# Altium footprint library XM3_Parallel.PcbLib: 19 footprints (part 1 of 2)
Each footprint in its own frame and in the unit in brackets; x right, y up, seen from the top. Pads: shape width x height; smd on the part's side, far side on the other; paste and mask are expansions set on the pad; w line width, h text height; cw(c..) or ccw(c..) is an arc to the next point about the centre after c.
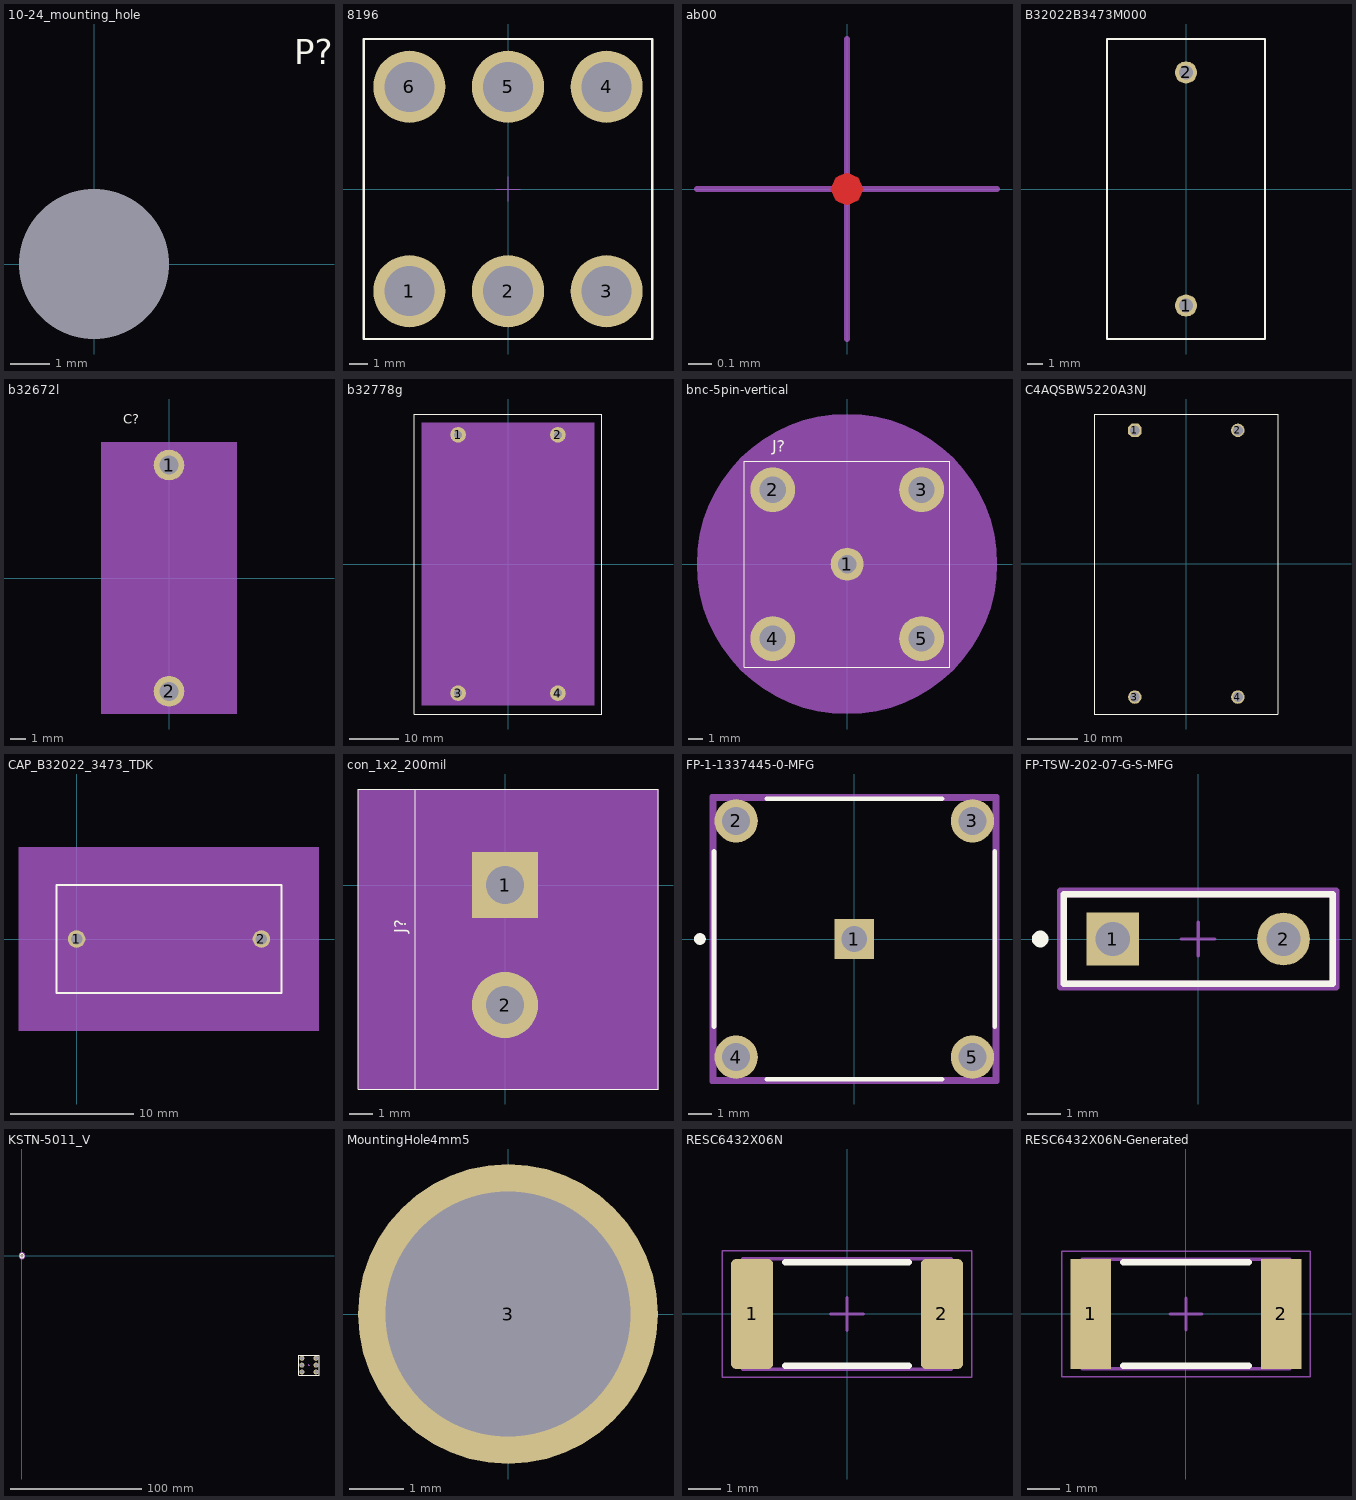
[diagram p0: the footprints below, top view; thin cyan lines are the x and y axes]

## 10-24_mounting_hole [mil]
pads (1):
  round 1 / inner round 60 / far side round 1 hole 150 square: ""(0,0)
Top Overlay:
  text "P?" at 200,200 h25
DRAWING_ORIGIN:
  lines w1: -25,0 25,0 ; 0,-25 0,25
PIN_NUMBER:

## 8196 [mil]
pads (6):
  round 150 / inner round 60 / far side round 150 hole 103.94: 1(-205,-212.5) 2(0,-212.5) 3(205,-212.5) 4(205,212.5) 5(0,212.5) 6(-205,212.5)
Top Overlay:
  lines w5: -300,311.02 -300,-311.81 300,-311.81 300,311.02 ; -300,311.81 300,311.81
DRAWING_ORIGIN:
  lines w1: -25,0 25,0 ; 0,-25 0,25
PIN_NUMBER:
  text "2" at -20,-212.5 h25
  text "6" at -225,212.5 h25
  text "5" at -20,212.5 h25
  text "3" at 185,-212.5 h25
  text "1" at -225,-212.5 h25
  text "4" at 185,212.5 h25
ASSEMBLY_TOP:
  text "J?" at 0,0 h25
3D body "8196-PCB-Conn-Color.STEP": height 453.5, standoff -216.5, extent -230.42,-278 239.58,261.95

## ab00 [mil]
TOP:
  region: 2.71,0 1.91,1.91 0,2.71 -1.26,2.18 -1.91,1.91 -2.71,0 -1.91,-1.91 -1.26,-2.18 0,-2.71 1.91,-1.91
DRAWING_ORIGIN:
  lines w1: -25,0 25,0 ; 0,-25 0,25

## B32022B3473M000 [mil]
pads (2):
  round 56 hole 36 mask+0: 1(0,-295.28) 2(0,295.28)
Top Overlay:
  lines w5: -200,-380 -180,-380 200,-380 200,380 -200,380 -200,-380
3D body "B32022B3473M000-ShortLeads.STEP": height 689.47, standoff -9.35, extent -177.17,-354.33 177.17,354.33

## b32672l [mil]
pads (2):
  round 80 / inner round 60 / far side round 80 hole 50 square: 1(0,295.28) 2(0,-295.28)
Top Overlay:
  text "C?" at -119,403.48 h25
DRAWING_ORIGIN:
  lines w1: -25,0 25,0 ; 0,-25 0,25
PIN_NUMBER:
  text "1" at -20,295.28 h25
  text "2" at -20,-295.28 h25
ASSEMBLY_TOP:
  dashed: 177.17,-354.33 177.17,354.33 -177.17,354.33 -177.17,-354.33

## b32778g [mil]
pads (4):
  round 125 / inner round 60 / far side round 125 hole 63: 1(-399.61,1033.46) 2(399.61,1033.46) 3(-399.61,-1033.46) 4(399.61,-1033.46)
Top Overlay:
  lines w5: -750,-1200 750,-1200 750,1200 -750,1200 -750,-1200
DRAWING_ORIGIN:
  lines w1: -25,0 25,0 ; 0,-25 0,25
PIN_NUMBER:
  text "4" at 379.61,-1033.46 h25
  text "1" at -419.61,1033.46 h25
  text "3" at -419.61,-1033.46 h25
  text "2" at 379.61,1033.46 h25
ASSEMBLY_TOP:
  dashed: 688.98,-1131.89 688.98,1131.89 -688.98,1131.89 -688.98,-1131.89
3D body "C4AQSBW5220A3NJ.STEP": height 1980.81, standoff -235.72, extent -697.83,-1145 700,1150.28

## bnc-5pin-vertical [mil]
pads (5):
  round 88 / inner round 60 / far side round 100 hole 50: 1(0,0)
  round 120 / inner round 60 / far side round 120 hole 70: 2(-199,199) 3(199,199) 4(-199,-199) 5(199,-199)
Top Overlay:
  lines w1: -275,-275 275,-275 275,275 -275,275 -275,-275
  text "J?" at -200,300 h31
PLACE_BOUND_TOP:
  region: 400.68,0.5 398.75,39.81 392.98,78.75 383.41,116.93 370.15,153.99 353.32,189.57 333.09,223.33 309.64,254.94 283.21,284.11 254.04,310.54 222.43,333.99 188.67,354.22 153.09,371.05 116.03,384.31 77.85,393.88 38.91,399.65 -0.4,401.58 -39.71,399.65 -78.65,393.88 -116.83,384.31 -153.89,371.05 -189.47,354.22 -200.73,347.48 -223.23,333.99 -254.84,310.54 -284.01,284.11 -310.44,254.94 -333.89,223.33 -354.12,189.57 -370.95,153.99 -384.21,116.93 -393.78,78.75 -399.55,39.81 -401.48,0.5 -399.55,-38.81 -393.78,-77.75 -384.21,-115.93 -370.95,-152.99 -354.12,-188.57 -333.89,-222.33 -310.44,-253.94 -284.01,-283.11 -254.84,-309.54 -223.23,-332.99 -200.73,-346.48 -189.47,-353.22 -153.89,-370.05 -116.83,-383.31 -78.65,-392.88 -39.71,-398.65 -0.4,-400.58 38.91,-398.65 77.85,-392.88 116.03,-383.31 153.09,-370.05 188.67,-353.22 222.43,-332.99 254.04,-309.54 283.21,-283.11 309.64,-253.94 333.09,-222.33 353.32,-188.57 370.15,-152.99 383.41,-115.93 392.98,-77.75 398.75,-38.81
  lines w1: 0,0 400,0
DRAWING_ORIGIN:
  lines w1: -25,0 25,0 ; 0,-25 0,25
PIN_NUMBER:
  text "2" at -219,199 h25
  text "5" at 179,-199 h25
  text "3" at 179,199 h25
  text "1" at -20,0 h25
  text "4" at -219,-199 h25
ASSEMBLY_TOP:
  lines w1: -275,-275 275,-275 275,275 -275,275 -275,-275
  text "J?" at -100,-175 h25
3D body: height 150, standoff 0, extent -401.48,-400.58 400.68,401.58

## C4AQSBW5220A3NJ [mm] "C4AQSBW5220A3NJ Unchecked Film; Metallized Polypropylene; DC Link; C4AQ; Automotive Grade; 22 uF; 5%; 1; 50 Film Capacitors 8.13"
pads (4):
  oct 2.65x2.65 hole 1.95: 1(-10.15,26.25)
  round 2.65 hole 1.95: 2(10.15,26.25) 3(-10.15,-26.25) 4(10.15,-26.25)
Top Overlay:
  lines w0.127: -18.161,-29.591 18.034,-29.591 18.034,29.464 -18.161,29.464 -18.161,-29.591
3D body "C4AQSBW5220A3NJ-ShortLeads.STEP": height 50.31, standoff -0.24, extent -17.725,-29.15 17.78,29.15

## CAP_B32022_3473_TDK [mil]
pads (2):
  round 56 hole 36 mask+0: 1(0,0) 2(590.55,0)
Top Overlay:
  lines w6: -64.22,-172.5 -64.22,172.5 654.78,172.5 654.78,-172.5 -64.22,-172.5
DFA_BOUND_TOP:
  region: 774.78,-292.5 -184.22,-292.5 -184.22,292.5 774.78,292.5
DRAWING_ORIGIN:
  lines w1: -59.22,-167.5 -59.22,167.5 649.78,167.5 649.78,-167.5 -59.22,-167.5
ASSEMBLY_DETAIL:
  region: 659.78,-177.5 -69.22,-177.5 -69.22,177.5 659.78,177.5
  lines w6: -69.22,-177.5 659.78,-177.5 659.78,177.5 -69.22,177.5 -69.22,-177.5
3D body "CAP_B32022_3473_TDK.step": height 570.98, standoff -177.99, extent -59.21,-167.48 649.76,167.48

## con_1x2_200mil [mil]
pads (2):
  rect 110.24x110.24 / inner round 60 / far side rect 110.24x110.24 hole 62.99: 1(0,0)
  round 110.24 / inner round 60 / far side round 110.24 hole 62.99: 2(0,-200)
Top Overlay:
  lines w1: -245,-340 -245,160 ; -245,-340 255,-340 255,160 -245,160 ; -245,-340 -245,160 ; -245,-340 -150,-340 -150,160 -245,160
  text "J?" at -165,-80 h20
DFA_BOUND_TOP:
  dashed: -125,-150 125,-150 125,50 -125,50
  region: -245,-340 255,-340 255,160 -245,160
PLACE_BOUND_TOP:
  region: -245,-340 255,-340 255,160 -245,160
DRAWING_ORIGIN:
  lines w1: -25,0 25,0 ; 0,-25 0,25
PIN_NUMBER:
  text "1" at -8,0 h20
  text "2" at -8,-200 h20
3D body: height 150, standoff 0, extent -245,-340 255,160

## FP-1-1337445-0-MFG [mm]
pads (5):
  rect 1.7x1.7 hole 1.1 paste-2539.97 mask+0: 1(0,0)
  round 1.85 hole 1.2 paste-2539.97 mask+0: 2(-5.05,5.05) 3(5.05,5.05) 4(-5.05,-5.05) 5(5.05,-5.05)
Top Overlay:
  circle w0.25: c-6.6,0 r0.125
  lines w0.2: -6,-3.75 -6,3.75 ; -3.75,-6 3.75,-6 ; -3.75,6 3.75,6 ; 6,-3.75 6,3.75
Top 3D Body:
  lines w0.2: -6,-6 6,-6 6,6 -6,6 -6,-6
Top Assembly:
  lines w0.2: -6.1,-6.1 6.1,-6.1 6.1,6.1 -6.1,6.1 -6.1,-6.1
  text ".Designator" at 0,0.188 h1
Top Courtyard:
  lines w0.2: -6.1,-6.1 6.1,-6.1 6.1,6.1 -6.1,6.1 -6.1,-6.1
Top Component Center:
  lines w0.1: -0.5,0 0.5,0 ; 0,-0.5 0,0.5
3D body "Conn_TE_Connectivity_1-1337445-0_eec.STEP": height 0.25, standoff 0, extent -6.1,-6.1 6.1,6.1

## FP-TSW-202-07-G-S-MFG [mm]
pads (2):
  rect 1.57x1.57 hole 1.02 paste-2539.97 mask+0: 1(-2.54,0)
  round 1.57 hole 1.02 paste-2539.97 mask+0: 2(2.54,0)
Top Overlay:
  circle w0.25: c-4.7,0 r0.125
  lines w0.2: -4,-1.335 -4,1.335 4,1.335 4,-1.335 -4,-1.335
Top 3D Body:
  lines w0.2: -4,-1.335 -4,1.335 4,1.335 4,-1.335 -4,-1.335
Top Assembly:
  lines w0.2: -4.1,-1.435 -4.1,1.435 4.1,1.435 4.1,-1.435 -4.1,-1.435
Top Courtyard:
  lines w0.2: -4.1,-1.435 -4.1,1.435 4.1,1.435 4.1,-1.435 -4.1,-1.435
Top Component Center:
  lines w0.1: -0.5,0 0.5,0 ; 0,-0.5 0,0.5
3D body "Conn_Samtec_TSW-202-07-G-S_eec.STEP": height 0.25, standoff 0, extent -4.1,-1.435 4.1,1.435

## KSTN-5011_V [mil] "Test Point, Dia 3.17mm"
height 325.98
pads (7):
  round 82.68 hole 62.99: 1(0,0)
  round 150 / inner round 60 / far side round 150 hole 103.94: 1(8812.5,-3480) 2(8812.5,-3275) 3(8812.5,-3070) 4(8387.5,-3070) 5(8387.5,-3275) 6(8387.5,-3480)
Top Overlay:
  circle w7.87: c0,0 r62.4
  lines w5: 8300,-3575 8300,-2975 8900,-2975 8900,-3575 8300,-3575
Top Assembly:
  text "J?" at 8600,-3275 h25
DRAWING_ORIGIN:
  circle w3.94: c0,0 r62.4
  lines w1: 8575,-3275 8625,-3275 ; 8600,-3300 8600,-3250
PIN_NUMBER:
  text "2" at 8812.5,-3295 h25
  text "6" at 8387.5,-3500 h25
  text "5" at 8387.5,-3295 h25
  text "3" at 8812.5,-3090 h25
  text "1" at 8812.5,-3500 h25
  text "4" at 8387.5,-3090 h25
ASSEMBLY_DETAIL:
  circle w1.97: c0,0 r88.58
  lines w3.94: -19.68,0 19.68,0 ; 0,-19.68 0,19.68
3D body "keystone-PN5011.STEP": height 320, standoff -125, extent -62.5,-62.49 62.5,62.51
3D body "8196-PCB-Conn-Color.STEP": height 453.5, standoff -216.5, extent 8338.05,-3505.42 8878,-3035.42

## MountingHole4mm5 [mm]
pads (1):
  round 5.5 hole 4.5: 3(0,0)

## RESC6432X06N [mm] "Chip Resistor, 2-Leads, Body 6.35x3.20mm, IPC Medium Density"
height 0.65
pads (2):
  rrect25% 1.3x3.4 smd: 1(-2.925,0) 2(2.925,0)
Top Overlay:
  lines w0.2: -1.9,-1.6 1.9,-1.6 ; -1.9,1.6 1.9,1.6
Top Assembly:
  lines w0.1: -3.225,-1.7 3.225,-1.7 3.225,1.7 -3.225,1.7 -3.225,-1.7
Top Courtyard:
  lines w0.05: -3.85,-1.95 3.85,-1.95 3.85,1.95 -3.85,1.95 -3.85,-1.95
  lines w0.1: -0.5,0 0.5,0 ; 0,-0.5 0,0.5
3D body "RESC6432X06N.step": height 0.65, standoff 0, extent -3.225,-1.7 3.225,1.7

## RESC6432X06N-Generated [mm] "Chip Resistor, 2-Leads, Body 6.35x3.20mm, IPC Medium Density"
height 0.65
pads (2):
  rect 1.25x3.4 smd: 1(-2.95,0) 2(2.95,0)
Top Overlay:
  lines w0.2: -1.95,-1.6 1.95,-1.6 ; -1.95,1.6 1.95,1.6
Top Assembly:
  lines w0.1: -3.225,-1.7 -3.225,1.7 3.225,1.7 3.225,-1.7 -3.225,-1.7
Top Courtyard:
  lines w0.05: -3.85,-1.95 -3.85,1.95 3.85,1.95 3.85,-1.95 -3.85,-1.95
  lines w0.1: -0.5,0 0.5,0 ; 0,-0.5 0,0.5
3D body "RESC6432X06N.step": height 0.65, standoff 0, extent -3.225,-1.7 3.225,1.7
